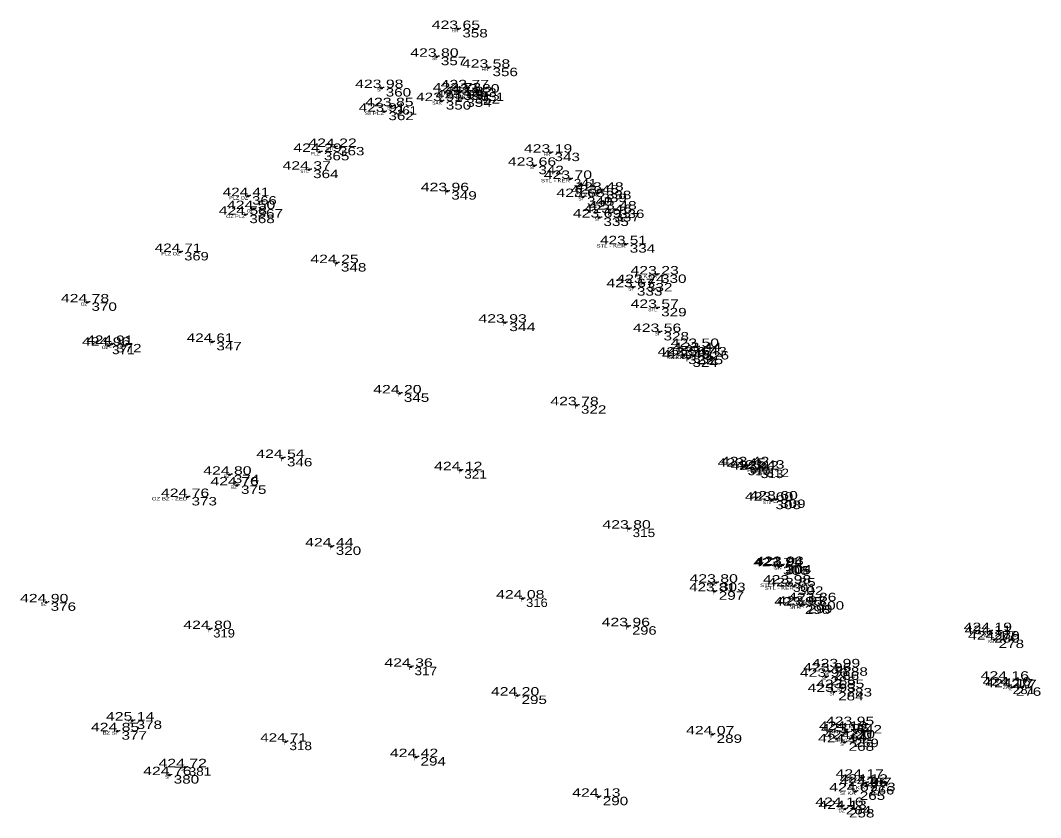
# Model space of a CAD drawing. Extents: x -639373 to -639056, y -1138651 to -1138359.
# Drawn here: x -639327.7 to -639237.1, y -1138429.7 to -1138358.9 of the extents above; entities that cross this region are included whole.
import ezdxf
from ezdxf.enums import TextEntityAlignment as Align

# ---------------------------------------------------------------- set-up
doc = ezdxf.new("R2010")
doc.units = 0
doc.header["$LTSCALE"] = 0.3
doc.header["$PDMODE"] = 32
doc.header["$PDSIZE"] = 0.15
for name, color, linetype in [('11', 7, 'Continuous'), ('12', 7, 'Continuous'), ('13', 7, 'Continuous'), ('14', 7, 'Continuous'), ('57', 7, 'Continuous')]:
    doc.layers.add(name, color=color, linetype=linetype)

msp = doc.modelspace()

# ---------------------------------------------------------------- linework, layer by layer
at = {"layer": '11'}
for p in [(-639288.83, -1138359.67), (-639290.74, -1138362.14), (-639286.15, -1138363.11), (-639295.64, -1138364.92), (-639288.04, -1138364.94), (-639288.74, -1138365.22), (-639288.48, -1138365.84), (-639287.74, -1138365.55), (-639287.1, -1138365.32), (-639294.74, -1138366.53), (-639290.3, -1138366.08), (-639295.4, -1138367.02), (-639299.79, -1138370.15), (-639301.13, -1138370.59), (-639280.64, -1138370.66), (-639302.09, -1138372.17), (-639282.07, -1138371.82), (-639278.88, -1138372.99), (-639289.81, -1138374.08), (-639276.07, -1138374.04), (-639307.49, -1138374.52), (-639277.75, -1138374.6), (-639276.47, -1138374.3), (-639307.03, -1138375.67), (-639274.91, -1138375.71), (-639307.76, -1138376.17), (-639276.29, -1138376.42), (-639275.32, -1138376.02), (-639313.53, -1138379.48), (-639273.95, -1138378.79), (-639299.62, -1138380.47), (-639272.42, -1138382.24), (-639271.17, -1138381.48), (-639273.31, -1138382.61), (-639321.79, -1138383.96), (-639271.16, -1138384.45), (-639284.68, -1138385.76), (-639270.95, -1138386.59), (-639319.6, -1138387.65), (-639310.69, -1138387.47), (-639319.92, -1138387.81), (-639268.76, -1138388.69), (-639267.91, -1138388.7), (-639267.59, -1138387.92), (-639267.39, -1138388.28), (-639268.38, -1138388.94), (-639294.03, -1138392.05), (-639278.29, -1138393.1), (-639304.42, -1138397.78), (-639263.43, -1138398.56), (-639263.13, -1138398.43), (-639309.14, -1138399.27), (-639288.62, -1138398.87), (-639262.27, -1138398.82), (-639261.77, -1138398.73), (-639308.5, -1138400.22), (-639312.9, -1138401.25), (-639261, -1138401.58), (-639260.59, -1138401.47), (-639273.66, -1138404.06), (-639300.08, -1138405.64), (-639260.33, -1138407.41), (-639260.14, -1138407.37), (-639260.06, -1138407.29), (-639265.92, -1138408.86), (-639259.4, -1138408.94), (-639259, -1138409.19), (-639283.11, -1138410.27), (-639266.04, -1138409.63), (-639325.42, -1138410.61), (-639258.39, -1138410.89), (-639258.11, -1138410.82), (-639257.16, -1138410.51), (-639310.91, -1138412.98), (-639273.73, -1138412.73), (-639241.56, -1138413.16), (-639241.56, -1138413.43), (-639241.17, -1138413.92), (-639293.04, -1138416.33), (-639255.82, -1138416.75), (-639255.05, -1138416.38), (-639256.12, -1138417.22), (-639240.05, -1138417.48), (-639255.43, -1138418.57), (-639254.68, -1138418.22), (-639239.88, -1138418.01), (-639239.64, -1138418.16), (-639283.57, -1138418.89), (-639317.78, -1138421.11), (-639319.12, -1138422.06), (-639254.42, -1138421.94), (-639254.24, -1138422.17), (-639253.8, -1138421.51), (-639304.16, -1138422.99), (-639266.23, -1138422.34), (-639254.5, -1138423.05), (-639253.99, -1138422.72), (-639292.55, -1138424.36), (-639313.11, -1138425.26), (-639314.48, -1138425.96), (-639252.94, -1138426.19), (-639252.59, -1138426.63), (-639253.51, -1138427.41), (-639252.61, -1138426.93), (-639276.35, -1138427.88), (-639254.75, -1138428.7), (-639254.47, -1138428.97)]:
    msp.add_point(p, dxfattribs=at)

# ---------------------------------------------------------------- texts
at = {"layer": '12'}
for s, width, p in [('423.65 ', 1.4, (-639288.83, -1138359.67)), ('423.98 ', 1.4, (-639295.64, -1138364.92)), ('423.85 ', 1.4, (-639294.74, -1138366.53)), ('423.91 ', 1.35, (-639290.299, -1138366.08)), ('423.91 ', 1.35, (-639295.399, -1138367.02)), ('424.22 ', 1.4, (-639299.79, -1138370.15)), ('424.29 ', 1.4, (-639301.13, -1138370.59)), ('424.37 ', 1.4, (-639302.09, -1138372.17)), ('424.41 ', 1.35, (-639307.489, -1138374.52)), ('423.45 ', 1.4, (-639276.47, -1138374.3)), ('423.48 ', 1.4, (-639276.07, -1138374.04)), ('424.50 ', 1.4, (-639307.03, -1138375.67)), ('423.48 ', 1.4, (-639274.91, -1138375.71)), ('423.46 ', 1.4, (-639275.319, -1138376.02)), ('424.71 ', 1.35, (-639313.529, -1138379.48)), ('423.23 ', 1.4, (-639271.17, -1138381.48)), ('423.24 ', 1.4, (-639272.42, -1138382.24)), ('424.78 ', 1.4, (-639321.79, -1138383.96)), ('424.96 ', 1.4, (-639319.919, -1138387.81)), ('424.91 ', 1.35, (-639319.599, -1138387.65)), ('423.50 ', 1.4, (-639267.59, -1138387.92)), ('423.44 ', 1.4, (-639267.39, -1138388.28)), ('423.50 ', 1.4, (-639268.76, -1138388.69)), ('423.48 ', 1.4, (-639268.38, -1138388.94)), ('423.47 ', 1.4, (-639267.91, -1138388.7)), ('423.42 ', 1.4, (-639262.27, -1138398.82)), ('423.43 ', 1.4, (-639261.77, -1138398.73)), ('424.76 ', 1.4, (-639312.899, -1138401.25)), ('423.60 ', 1.4, (-639260.59, -1138401.47)), ('423.80 ', 1.4, (-639265.92, -1138408.86)), ('424.90 ', 1.4, (-639325.42, -1138410.61)), ('423.86 ', 1.4, (-639257.159, -1138410.51)), ('424.19 ', 1.4, (-639241.56, -1138413.16)), ('424.11 ', 1.35, (-639241.559, -1138413.43)), ('424.17 ', 1.4, (-639241.17, -1138413.92)), ('423.99 ', 1.4, (-639255.05, -1138416.38)), ('424.16 ', 1.4, (-639240.049, -1138417.48)), ('423.85 ', 1.4, (-639254.68, -1138418.22)), ('424.16 ', 1.4, (-639239.879, -1138418.01)), ('424.17 ', 1.4, (-639239.64, -1138418.16)), ('425.14 ', 1.4, (-639317.78, -1138421.11)), ('424.19 ', 1.4, (-639254.42, -1138421.94)), ('423.95 ', 1.4, (-639253.8, -1138421.51)), ('424.85 ', 1.4, (-639319.12, -1138422.06)), ('423.95 ', 1.4, (-639254.24, -1138422.17)), ('424.72 ', 1.4, (-639313.11, -1138425.26)), ('424.76 ', 1.4, (-639314.479, -1138425.96)), ('424.07 ', 1.4, (-639253.51, -1138427.41)), ('424.06 ', 1.4, (-639252.609, -1138426.93)), ('424.12 ', 1.4, (-639252.59, -1138426.63)), ('424.13 ', 1.4, (-639254.47, -1138428.97))]:
    msp.add_text(s, height=0.75, dxfattribs=dict(at, width=width)).set_placement(p, align=Align.CENTER)
at = {"layer": '13'}
for s, width, p in [(' 358', 1.35, (-639288.83, -1138360.42)), (' 357', 1.35, (-639290.74, -1138362.89)), (' 356', 1.35, (-639286.15, -1138363.86)), (' 360', 1.35, (-639295.64, -1138365.67)), (' 353', 1.35, (-639288.04, -1138365.69)), (' 355', 1.35, (-639288.74, -1138365.97)), (' 354', 1.35, (-639288.48, -1138366.59)), (' 352', 1.35, (-639287.74, -1138366.3)), (' 351', 1.2, (-639287.1, -1138366.07)), (' 361', 1.15, (-639294.74, -1138367.28)), (' 350', 1.35, (-639290.3, -1138366.83)), (' 362', 1.35, (-639295.4, -1138367.77)), (' 363', 1.35, (-639299.79, -1138370.9)), (' 365', 1.35, (-639301.13, -1138371.34)), (' 343', 1.35, (-639280.64, -1138371.41)), (' 364', 1.35, (-639302.09, -1138372.92)), (' 342', 1.35, (-639282.07, -1138372.57)), (' 341', 1.2, (-639278.88, -1138373.74)), (' 349', 1.35, (-639289.81, -1138374.83)), (' 338', 1.35, (-639276.07, -1138374.79)), (' 366', 1.3, (-639307.49, -1138375.27)), (' 340', 1.35, (-639277.75, -1138375.35)), (' 339', 1.35, (-639276.47, -1138375.05)), (' 367', 1.35, (-639307.03, -1138376.42)), (' 336', 1.35, (-639274.91, -1138376.46)), (' 368', 1.35, (-639307.76, -1138376.92)), (' 335', 1.35, (-639276.29, -1138377.17)), (' 337', 1.35, (-639275.32, -1138376.77)), (' 369', 1.3, (-639313.53, -1138380.23)), (' 334', 1.35, (-639273.95, -1138379.54)), (' 348', 1.35, (-639299.62, -1138381.22)), (' 332', 1.35, (-639272.42, -1138382.99)), (' 330', 1.35, (-639271.17, -1138382.23)), (' 333', 1.35, (-639273.31, -1138383.36)), (' 370', 1.35, (-639321.79, -1138384.71)), (' 329', 1.35, (-639271.16, -1138385.2)), (' 344', 1.4, (-639284.68, -1138386.51)), (' 328', 1.35, (-639270.95, -1138387.34)), (' 372', 1.35, (-639319.6, -1138388.4)), (' 347', 1.35, (-639310.69, -1138388.22)), (' 371', 1.2, (-639319.92, -1138388.56)), (' 643', 1.35, (-639267.59, -1138388.67)), (' 326', 1.35, (-639267.39, -1138389.03)), (' 323', 1.35, (-639268.76, -1138389.44)), (' 324', 1.35, (-639268.38, -1138389.69)), (' 325', 1.35, (-639267.91, -1138389.45)), (' 345', 1.35, (-639294.03, -1138392.8)), (' 322', 1.35, (-639278.29, -1138393.85)), (' 346', 1.35, (-639304.42, -1138398.53)), (' 310', 1.2, (-639263.43, -1138399.31)), (' 374', 1.35, (-639309.14, -1138400.02)), (' 321', 1.2, (-639288.62, -1138399.62)), (' 313', 1.2, (-639262.27, -1138399.57)), (' 312', 1.2, (-639261.77, -1138399.48)), (' 375', 1.35, (-639308.5, -1138400.97)), (' 373', 1.35, (-639312.9, -1138402)), (' 308', 1.35, (-639261, -1138402.33)), (' 309', 1.35, (-639260.59, -1138402.22)), (' 315', 1.2, (-639273.66, -1138404.81)), (' 320', 1.35, (-639300.08, -1138406.39)), (' 306', 1.35, (-639260.33, -1138408.16)), (' 305', 1.35, (-639260.14, -1138408.12)), (' 304', 1.35, (-639260.06, -1138408.04)), (' 303', 1.35, (-639265.92, -1138409.61)), (' 301', 1.2, (-639259.4, -1138409.69)), (' 302', 1.35, (-639259, -1138409.94)), (' 316', 1.15, (-639283.11, -1138411.02)), (' 297', 1.35, (-639266.04, -1138410.38)), (' 376', 1.35, (-639325.42, -1138411.36)), (' 298', 1.35, (-639258.39, -1138411.64)), (' 299', 1.3, (-639258.11, -1138411.57)), (' 300', 1.35, (-639257.16, -1138411.26)), (' 319', 1.15, (-639310.91, -1138413.73)), (' 296', 1.3, (-639273.73, -1138413.48)), (' 279', 1.35, (-639241.56, -1138413.91)), (' 280', 1.35, (-639241.56, -1138414.18)), (' 278', 1.35, (-639241.17, -1138414.67)), (' 317', 1.2, (-639293.04, -1138417.08)), (' 288', 1.35, (-639255.05, -1138417.13)), (' 285', 1.35, (-639256.12, -1138417.97)), (' 286', 1.35, (-639255.82, -1138417.5)), (' 277', 1.35, (-639240.05, -1138418.23)), (' 283', 1.35, (-639254.68, -1138418.97)), (' 281', 1.2, (-639239.88, -1138418.76)), (' 276', 1.35, (-639239.64, -1138418.91)), (' 295', 1.35, (-639283.57, -1138419.64)), (' 284', 1.35, (-639255.43, -1138419.32)), (' 378', 1.35, (-639317.78, -1138421.86)), (' 377', 1.35, (-639319.12, -1138422.81)), (' 270', 1.35, (-639254.42, -1138422.69)), (' 641', 1.2, (-639254.24, -1138422.92)), (' 642', 1.35, (-639253.8, -1138422.26)), (' 318', 1.2, (-639304.16, -1138423.74)), (' 289', 1.35, (-639266.23, -1138423.09)), (' 268', 1.35, (-639254.5, -1138423.8)), (' 269', 1.3, (-639253.99, -1138423.47)), (' 294', 1.35, (-639292.55, -1138425.11)), (' 381', 1.2, (-639313.11, -1138426.01)), (' 380', 1.35, (-639314.48, -1138426.71)), (' 267', 1.35, (-639252.94, -1138426.94)), (' 273', 1.35, (-639252.59, -1138427.38)), (' 265', 1.35, (-639253.51, -1138428.16)), (' 266', 1.3, (-639252.61, -1138427.68)), (' 290', 1.35, (-639276.35, -1138428.63)), (' 264', 1.35, (-639254.75, -1138429.45)), (' 258', 1.35, (-639254.47, -1138429.72))]:
    msp.add_text(s, height=0.75, dxfattribs=dict(at, width=width)).set_placement(p)
msp.add_text(' 311', height=0.75, dxfattribs=at).set_placement((-639263.13, -1138399.18))
at = {"layer": '14'}
for s, width, p in [('423.80 ', 1.4, (-639290.74, -1138362.14)), ('423.58 ', 1.4, (-639286.15, -1138363.11)), ('423.73 ', 1.4, (-639288.74, -1138365.22)), ('423.77 ', 1.4, (-639288.04, -1138364.94)), ('423.82 ', 1.4, (-639287.74, -1138365.55)), ('423.80 ', 1.4, (-639287.1, -1138365.32)), ('423.93 ', 1.4, (-639288.48, -1138365.84)), ('423.19 ', 1.4, (-639280.64, -1138370.66)), ('423.66 ', 1.4, (-639282.069, -1138371.82)), ('423.70 ', 1.4, (-639278.88, -1138372.99)), ('423.96 ', 1.4, (-639289.809, -1138374.08)), ('423.65 ', 1.4, (-639277.75, -1138374.6)), ('424.58 ', 1.4, (-639307.76, -1138376.17)), ('423.69 ', 1.4, (-639276.29, -1138376.42)), ('423.51 ', 1.35, (-639273.949, -1138378.79)), ('424.25 ', 1.4, (-639299.62, -1138380.47)), ('423.67 ', 1.4, (-639273.31, -1138382.61)), ('423.57 ', 1.4, (-639271.16, -1138384.45)), ('423.93 ', 1.4, (-639284.68, -1138385.76)), ('423.56 ', 1.4, (-639270.949, -1138386.59)), ('424.61 ', 1.35, (-639310.689, -1138387.47)), ('424.20 ', 1.4, (-639294.03, -1138392.05)), ('423.78 ', 1.4, (-639278.29, -1138393.1)), ('424.54 ', 1.4, (-639304.42, -1138397.78)), ('423.42 ', 1.4, (-639263.13, -1138398.43)), ('424.80 ', 1.4, (-639309.14, -1138399.27)), ('424.12 ', 1.4, (-639288.62, -1138398.87)), ('423.45 ', 1.4, (-639263.43, -1138398.56)), ('424.76 ', 1.4, (-639308.499, -1138400.22)), ('423.60 ', 1.4, (-639261, -1138401.58)), ('423.80 ', 1.4, (-639273.66, -1138404.06)), ('424.44 ', 1.4, (-639300.08, -1138405.64)), ('423.71 ', 1.35, (-639260.329, -1138407.41)), ('423.94 ', 1.4, (-639260.14, -1138407.37)), ('423.93 ', 1.4, (-639260.06, -1138407.29)), ('423.98 ', 1.4, (-639259.4, -1138408.94)), ('423.85 ', 1.4, (-639259, -1138409.19)), ('423.81 ', 1.35, (-639266.039, -1138409.63)), ('424.08 ', 1.4, (-639283.11, -1138410.27)), ('423.95 ', 1.4, (-639258.39, -1138410.89)), ('423.93 ', 1.4, (-639258.11, -1138410.82)), ('423.96 ', 1.4, (-639273.729, -1138412.73)), ('424.80 ', 1.4, (-639310.91, -1138412.98)), ('424.36 ', 1.4, (-639293.039, -1138416.33)), ('423.96 ', 1.4, (-639256.119, -1138417.22)), ('423.96 ', 1.4, (-639255.819, -1138416.75)), ('424.20 ', 1.4, (-639283.57, -1138418.89)), ('423.93 ', 1.4, (-639255.43, -1138418.57)), ('424.07 ', 1.4, (-639266.23, -1138422.34)), ('424.20 ', 1.4, (-639253.99, -1138422.72)), ('424.71 ', 1.35, (-639304.159, -1138422.99)), ('424.14 ', 1.4, (-639254.5, -1138423.05)), ('424.42 ', 1.4, (-639292.55, -1138424.36)), ('424.17 ', 1.4, (-639252.94, -1138426.19)), ('424.13 ', 1.4, (-639276.35, -1138427.88)), ('424.16 ', 1.4, (-639254.749, -1138428.7))]:
    msp.add_text(s, height=0.75, dxfattribs=dict(at, width=width)).set_placement(p, align=Align.CENTER)
at = {"layer": '57'}
for s, width, p in [('HR', 0.85, (-639288.829, -1138359.97)), ('SI', 1.05, (-639290.74, -1138362.44)), ('HR', 0.85, (-639286.149, -1138363.41)), ('SI', 1.05, (-639295.64, -1138365.22)), ('K', 0.65, (-639288.039, -1138365.24)), ('K KA SI', 1.35, (-639288.74, -1138365.52)), ('SI K KA', 1.4, (-639287.74, -1138365.85)), ('KA', 0.95, (-639288.48, -1138366.14)), ('SI', 1.05, (-639287.1, -1138365.62)), ('SI', 1.05, (-639294.74, -1138366.83)), ('SI PLZ', 1.4, (-639295.399, -1138367.32)), ('STL', 1.05, (-639299.789, -1138370.45)), ('PLZ', 1.1, (-639301.129, -1138370.89)), ('HR', 0.85, (-639280.639, -1138370.96)), ('STL', 1.05, (-639302.089, -1138372.47)), ('SI', 1.05, (-639282.07, -1138372.12)), ('STL - KER', 1.35, (-639278.879, -1138373.29)), ('T', 0.85, (-639289.81, -1138374.38)), ('KA', 0.95, (-639276.07, -1138374.34)), ('PLZ OZ', 1.2, (-639307.489, -1138374.82)), ('KA K HR', 1.25, (-639276.469, -1138374.6)), ('SI', 1.05, (-639277.75, -1138374.9)), ('OZ', 0.9, (-639307.029, -1138375.97)), ('KA', 0.95, (-639274.91, -1138376.01)), ('OZ PLZ', 1.2, (-639307.759, -1138376.47)), ('SI', 1.05, (-639276.29, -1138376.72)), ('K', 0.65, (-639275.319, -1138376.32)), ('PLZ OZ', 1.2, (-639313.529, -1138379.78)), ('STL - KER', 1.35, (-639273.949, -1138379.09)), ('T', 0.85, (-639299.62, -1138380.77)), ('PL K KA', 1.3, (-639271.17, -1138381.78)), ('K', 0.65, (-639272.419, -1138382.54)), ('SI', 1.05, (-639273.31, -1138382.91)), ('OZ', 0.9, (-639321.789, -1138384.26)), ('STL', 1.05, (-639271.159, -1138384.75)), ('T', 0.85, (-639284.68, -1138386.06)), ('SI', 1.05, (-639270.95, -1138386.89)), ('OZ', 0.9, (-639319.599, -1138387.95)), ('T', 0.85, (-639310.69, -1138387.77)), ('OZ', 0.9, (-639319.919, -1138388.11)), ('K PL', 1.25, (-639267.589, -1138388.22)), ('K PL', 1.25, (-639267.389, -1138388.58)), ('SI KA', 1.35, (-639268.76, -1138388.99)), ('K CH', 1.1, (-639267.909, -1138389)), ('K', 0.65, (-639268.379, -1138389.24)), ('T', 0.85, (-639294.03, -1138392.35)), ('T', 0.85, (-639278.29, -1138393.4)), ('T', 0.85, (-639304.42, -1138398.08)), ('SI', 1.05, (-639263.43, -1138398.86)), ('K', 0.65, (-639263.129, -1138398.73)), ('T', 0.85, (-639288.62, -1138399.17)), ('PL CH', 1.15, (-639261.769, -1138399.03)), ('CH', 0.8, (-639262.269, -1138399.12)), ('OZ BZ - ZED', 1.35, (-639312.9, -1138401.55)), ('STL', 1.05, (-639260.999, -1138401.88)), ('T', 0.85, (-639273.66, -1138404.36)), ('T', 0.85, (-639300.08, -1138405.94)), ('STL', 1.05, (-639260.059, -1138407.59)), ('SI', 1.05, (-639260.33, -1138407.71)), ('K', 0.65, (-639260.139, -1138407.67)), ('STL - KER', 1.35, (-639259.399, -1138409.24)), ('STL - KER', 1.35, (-639258.999, -1138409.49)), ('T', 0.85, (-639283.11, -1138410.57)), ('T', 0.85, (-639266.04, -1138409.93)), ('SI K', 1.3, (-639258.389, -1138411.19)), ('K CH', 1.1, (-639258.109, -1138411.12)), ('CH PL', 1.15, (-639257.159, -1138410.81)), ('T', 0.85, (-639310.91, -1138413.28)), ('T', 0.85, (-639273.73, -1138413.03)), ('KB KC', 1.15, (-639241.559, -1138413.46)), ('KB', 0.9, (-639241.169, -1138414.22)), ('T', 0.85, (-639293.04, -1138416.63)), ('SI', 1.05, (-639256.12, -1138417.52)), ('SI', 1.05, (-639255.82, -1138417.05)), ('K KA', 1.2, (-639240.05, -1138417.78)), ('PL SI', 1.3, (-639254.68, -1138418.52)), ('K', 0.65, (-639239.639, -1138418.46)), ('T', 0.85, (-639283.57, -1138419.19)), ('SI', 1.05, (-639255.43, -1138418.87)), ('SI', 1.05, (-639317.78, -1138421.41)), ('BZ SI', 1.3, (-639319.12, -1138422.36)), ('SI KC', 1.35, (-639254.419, -1138422.24)), ('PL K', 1.25, (-639253.799, -1138421.81)), ('T', 0.85, (-639304.16, -1138423.29)), ('T', 0.85, (-639266.23, -1138422.64)), ('SI KB', 1.35, (-639253.989, -1138423.02)), ('SI', 1.05, (-639254.5, -1138423.35)), ('T', 0.85, (-639292.55, -1138424.66)), ('SI', 1.05, (-639313.11, -1138425.56)), ('SI', 1.05, (-639314.48, -1138426.26)), ('SI KA', 1.35, (-639252.94, -1138426.49)), ('SI KA', 1.35, (-639253.51, -1138427.71)), ('SI K K', 1.35, (-639252.609, -1138427.23)), ('T', 0.85, (-639276.35, -1138428.18)), ('SI', 1.05, (-639254.75, -1138429)), ('DZ', 0.9, (-639254.469, -1138429.27))]:
    msp.add_text(s, height=0.3, dxfattribs=dict(at, width=width)).set_placement(p, align=Align.RIGHT)
for s, p in [('SAK', (-639290.299, -1138366.38)), ('BZ', (-639309.139, -1138399.57)), ('BZ', (-639308.499, -1138400.52)), ('PL', (-639260.589, -1138401.77)), ('SAK', (-639265.919, -1138409.16)), ('BZ', (-639325.419, -1138410.91)), ('ZAA', (-639241.56, -1138413.73)), ('PL', (-639255.049, -1138416.68)), ('ZA', (-639239.88, -1138418.31)), ('ZA', (-639254.24, -1138422.47)), ('ZA', (-639252.59, -1138426.93))]:
    msp.add_text(s, height=0.3, dxfattribs=at).set_placement(p, align=Align.RIGHT)

doc.saveas('drawing.dxf')
